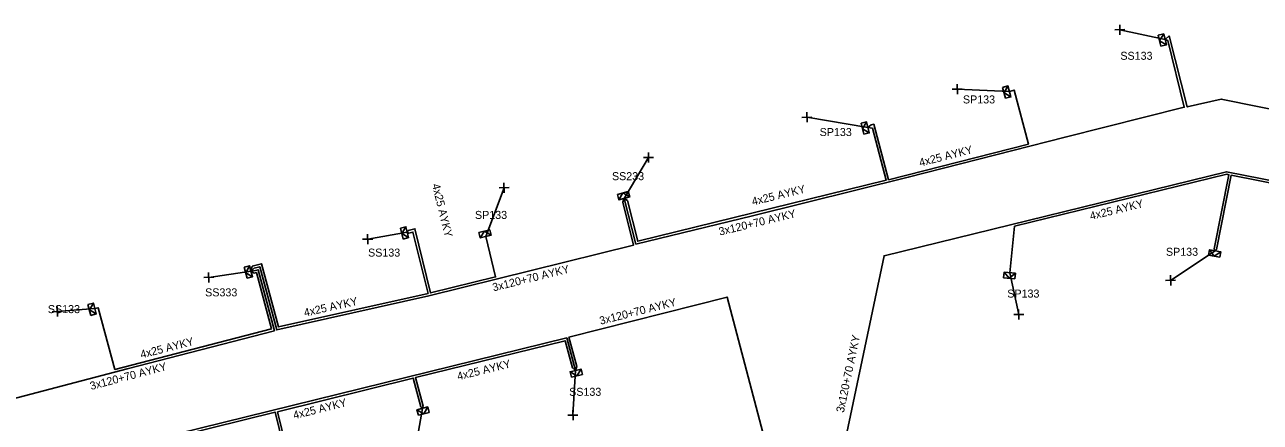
# Model space of a CAD drawing. Extents: x -762500 to -761285, y -1155006 to -1154135.
# Drawn here: x -762207.7 to -762054.2, y -1154659.6 to -1154610.3 of the extents above; entities that cross this region are included whole.
import ezdxf

# ---------------------------------------------------------------- set-up
doc = ezdxf.new("R2010")
doc.units = 0
for name, color, linetype in [('Vrstva 31', 7, 'Continuous'), ('Vrstva 33', 7, 'Continuous'), ('Vrstva 34', 7, 'Continuous'), ('Vrstva 5', 7, 'Continuous'), ('Vrstva 59', 7, 'Continuous'), ('Vrstva 6', 7, 'Continuous')]:
    doc.layers.add(name, color=color, linetype=linetype)

msp = doc.modelspace()

# ---------------------------------------------------------------- linework, layer by layer
at = {"layer": 'Vrstva 31'}
for points in [[(-762066.92, -1154611.568), (-762066.24, -1154611.398), (-762065.902, -1154612.757), (-762066.581, -1154612.926)], [(-762066.92, -1154611.568), (-762066.581, -1154612.926)], [(-762066.75, -1154612.247), (-762066.24, -1154611.398)], [(-762066.75, -1154612.247), (-762065.902, -1154612.757)], [(-762086.258, -1154618.042), (-762085.582, -1154617.861), (-762085.22, -1154619.213), (-762085.896, -1154619.395)], [(-762086.258, -1154618.042), (-762085.896, -1154619.395)], [(-762086.077, -1154618.719), (-762085.582, -1154617.861)], [(-762086.077, -1154618.719), (-762085.22, -1154619.213)], [(-762103.83, -1154622.497), (-762103.151, -1154622.328), (-762102.812, -1154623.686), (-762103.491, -1154623.855)], [(-762103.83, -1154622.497), (-762103.491, -1154623.855)], [(-762103.661, -1154623.176), (-762103.151, -1154622.328)], [(-762103.661, -1154623.176), (-762102.812, -1154623.686)], [(-762132.753, -1154630.971), (-762134.105, -1154631.333)], [(-762132.753, -1154630.971), (-762132.571, -1154631.647), (-762133.924, -1154632.01), (-762134.105, -1154631.333)], [(-762133.429, -1154631.152), (-762133.924, -1154632.01)], [(-762133.429, -1154631.152), (-762132.571, -1154631.647)], [(-762161.06, -1154635.507), (-762160.381, -1154635.338), (-762160.042, -1154636.696), (-762160.721, -1154636.866)], [(-762161.06, -1154635.507), (-762160.721, -1154636.866)], [(-762160.891, -1154636.187), (-762160.381, -1154635.338)], [(-762160.891, -1154636.187), (-762160.042, -1154636.696)], [(-762149.947, -1154635.71), (-762151.306, -1154636.049)], [(-762149.947, -1154635.71), (-762149.778, -1154636.389), (-762151.136, -1154636.728), (-762151.306, -1154636.049)], [(-762150.626, -1154635.88), (-762151.136, -1154636.728)], [(-762150.626, -1154635.88), (-762149.778, -1154636.389)], [(-762060.654, -1154638.887), (-762060.532, -1154638.198), (-762059.154, -1154638.441), (-762059.275, -1154639.13)], [(-762060.654, -1154638.887), (-762059.275, -1154639.13)], [(-762059.965, -1154639.009), (-762060.532, -1154638.198)], [(-762059.965, -1154639.009), (-762059.154, -1154638.441)], [(-762180.468, -1154640.372), (-762179.792, -1154640.191), (-762179.43, -1154641.543), (-762180.106, -1154641.725)], [(-762180.468, -1154640.372), (-762180.106, -1154641.725)], [(-762180.287, -1154641.048), (-762179.792, -1154640.191)], [(-762180.287, -1154641.048), (-762179.43, -1154641.543)], [(-762086.122, -1154641.673), (-762086.049, -1154640.977), (-762084.657, -1154641.123), (-762084.73, -1154641.82)], [(-762085.426, -1154641.746), (-762086.049, -1154640.977)], [(-762085.426, -1154641.746), (-762084.657, -1154641.123)], [(-762086.122, -1154641.673), (-762084.73, -1154641.82)], [(-762199.888, -1154645.002), (-762199.212, -1154644.821), (-762198.85, -1154646.173), (-762199.526, -1154646.354)], [(-762199.888, -1154645.002), (-762199.526, -1154646.354)], [(-762199.707, -1154645.678), (-762199.212, -1154644.821)], [(-762199.707, -1154645.678), (-762198.85, -1154646.173)], [(-762139.812, -1154654.04), (-762139.982, -1154653.36), (-762138.623, -1154653.022), (-762138.454, -1154653.701)], [(-762139.133, -1154653.87), (-762139.982, -1154653.36)], [(-762139.133, -1154653.87), (-762138.623, -1154653.022)], [(-762139.812, -1154654.04), (-762138.454, -1154653.701)], [(-762158.828, -1154658.759), (-762159.009, -1154658.083), (-762157.657, -1154657.72), (-762157.476, -1154658.397)], [(-762158.152, -1154658.578), (-762157.657, -1154657.72)], [(-762158.152, -1154658.578), (-762159.009, -1154658.083)], [(-762158.828, -1154658.759), (-762157.476, -1154658.397)]]:
    msp.add_lwpolyline(points, dxfattribs=at)
at = {"layer": 'Vrstva 34'}
for points in [[(-762071.679, -1154611.505), (-762071.701, -1154610.255)], [(-762072.315, -1154610.891), (-762071.065, -1154610.869)], [(-762091.869, -1154618.875), (-762091.891, -1154617.625)], [(-762092.505, -1154618.261), (-762091.255, -1154618.239)], [(-762110.549, -1154622.375), (-762110.571, -1154621.125)], [(-762111.185, -1154621.761), (-762109.935, -1154621.739)], [(-762130.875, -1154626.761), (-762129.625, -1154626.739)], [(-762130.239, -1154627.375), (-762130.261, -1154626.125)], [(-762148.179, -1154631.125), (-762148.201, -1154629.875)], [(-762148.815, -1154630.511), (-762147.565, -1154630.489)], [(-762165.119, -1154637.505), (-762165.141, -1154636.255)], [(-762165.755, -1154636.891), (-762164.505, -1154636.869)], [(-762184.869, -1154642.255), (-762184.891, -1154641.005)], [(-762185.505, -1154641.641), (-762184.255, -1154641.619)], [(-762066.005, -1154642.011), (-762064.755, -1154641.989)], [(-762065.369, -1154642.625), (-762065.391, -1154641.375)], [(-762203.679, -1154646.505), (-762203.701, -1154645.255)], [(-762084.239, -1154646.875), (-762084.261, -1154645.625)], [(-762204.315, -1154645.891), (-762203.065, -1154645.869)], [(-762084.875, -1154646.261), (-762083.625, -1154646.239)], [(-762140.255, -1154658.761), (-762139.005, -1154658.739)], [(-762139.619, -1154659.375), (-762139.641, -1154658.125)]]:
    msp.add_lwpolyline(points, dxfattribs=at)
at = {"layer": 'Vrstva 5'}
for points in [[(-762014.3, -1154621.08), (-762015.05, -1154620.95), (-762016.45, -1154628.07), (-762035.28, -1154624.27), (-762044.53, -1154622.42), (-762059.09, -1154619.49), (-762063.31, -1154620.47), (-762065.57, -1154611.64), (-762066.07, -1154612.08), (-762065.74, -1154612.2), (-762063.68, -1154620.51), (-762078.48, -1154624.21), (-762097.97, -1154629.2), (-762117.33, -1154634), (-762131.8, -1154637.5), (-762133.25, -1154631.83)], [(-762133.25, -1154631.83), (-762132.87, -1154632.1), (-762131.58, -1154637.14), (-762100.71, -1154629.57), (-762102.43, -1154623.11), (-762102.98, -1154623.01), (-762102.56, -1154622.7), (-762102.25, -1154622.61), (-762100.42, -1154629.51), (-762083.05, -1154625.07), (-762084.82, -1154618.37), (-762085.4, -1154618.54)], [(-762018.03, -1154646.45), (-762017.58, -1154646.23), (-762016.49, -1154646.47), (-762014.67, -1154637.34), (-762032.87, -1154633.54), (-762058.42, -1154628.52), (-762100.97, -1154638.95), (-762109.63, -1154679.98), (-762106.75, -1154684.45), (-762093.8, -1154686.97), (-762093.14, -1154686.59)], [(-762018.03, -1154646.45), (-762017.74, -1154645.89), (-762016.72, -1154646.11), (-762015.02, -1154637.57), (-762032.64, -1154633.9), (-762034.29, -1154641.96), (-762035.28, -1154641.78), (-762035.4, -1154641.56), (-762035.09, -1154641.51), (-762034.53, -1154641.61), (-762032.93, -1154633.85), (-762057.86, -1154628.94), (-762059.66, -1154638.15), (-762059.84, -1154638.32), (-762059.95, -1154638.09), (-762058.14, -1154628.89), (-762058.41, -1154628.83), (-762084.76, -1154635.28), (-762085.35, -1154641.05)], [(-762133.25, -1154631.83), (-762133.45, -1154632.29), (-762132.09, -1154637.62), (-762157.55, -1154643.93), (-762176.42, -1154648.15), (-762178.53, -1154640.31), (-762179.23, -1154640.5), (-762179.61, -1154640.87)], [(-762179.61, -1154640.87), (-762179.48, -1154640.25), (-762178.32, -1154639.94), (-762176.2, -1154647.79), (-762157.62, -1154643.63), (-762159.5, -1154636.01), (-762160.01, -1154636.14), (-762160.21, -1154636.02), (-762160.08, -1154635.81), (-762159.27, -1154635.6), (-762157.33, -1154643.57), (-762149.24, -1154641.58), (-762150.46, -1154636.56)], [(-762179.61, -1154640.87), (-762179.07, -1154640.76), (-762178.74, -1154640.68), (-762176.71, -1154648.25), (-762194.99, -1154652.98), (-762214.28, -1154658.05), (-762215.36, -1154658.34), (-762217.56, -1154649.51), (-762218.27, -1154649.71), (-762218.34, -1154649.89)], [(-762199.03, -1154645.5), (-762198.62, -1154645.4), (-762196.53, -1154653.07), (-762177.08, -1154648.04), (-762178.95, -1154641.04), (-762179.24, -1154641.1), (-762179.61, -1154640.87)], [(-762139.3, -1154653.19), (-762139.13, -1154652.68), (-762140.12, -1154649.04), (-762120.48, -1154644.08), (-762115.24, -1154663.87), (-762118.83, -1154679.7), (-762119.29, -1154679.92)], [(-762223.4, -1154669.64), (-762222.98, -1154669.48), (-762140.4, -1154649.15), (-762139.3, -1154653.19)], [(-762139.3, -1154653.19), (-762139.7, -1154652.86), (-762140.61, -1154649.51), (-762159.19, -1154654.08), (-762158.25, -1154657.62), (-762158.33, -1154657.9), (-762158.54, -1154657.7), (-762159.49, -1154654.13), (-762176.33, -1154658.33), (-762174.77, -1154664.73), (-762175.35, -1154664.79), (-762175.14, -1154664.47), (-762176.64, -1154658.36), (-762192.36, -1154662.25), (-762190.04, -1154671.92), (-762190.54, -1154672.04)]]:
    msp.add_lwpolyline(points, dxfattribs=at)
at = {"layer": 'Vrstva 59'}
for points in [[(-762066.07, -1154612.08), (-762071.69, -1154610.88)], [(-762085.4, -1154618.54), (-762091.88, -1154618.25)], [(-762102.98, -1154623.01), (-762110.56, -1154621.75)], [(-762133.25, -1154631.83), (-762130.25, -1154626.75)], [(-762150.46, -1154636.56), (-762148.19, -1154630.5)], [(-762160.21, -1154636.02), (-762165.13, -1154636.88)], [(-762059.84, -1154638.32), (-762065.38, -1154642)], [(-762179.61, -1154640.87), (-762184.88, -1154641.63)], [(-762085.35, -1154641.05), (-762084.25, -1154646.25)], [(-762199.03, -1154645.5), (-762203.69, -1154645.88)], [(-762139.3, -1154653.19), (-762139.63, -1154658.75)], [(-762158.33, -1154657.9), (-762159.44, -1154664.25)]]:
    msp.add_lwpolyline(points, dxfattribs=at)

# ---------------------------------------------------------------- texts
at = {"layer": 'Vrstva 33'}
for s, p in [('SS133', (-762071.62, -1154614.61)), ('SP133', (-762091.18, -1154620.03)), ('SP133', (-762108.98, -1154624.08)), ('SS233', (-762134.78, -1154629.56)), ('SP133', (-762151.8, -1154634.37)), ('SS133', (-762165.08, -1154639.05)), ('SP133', (-762065.96, -1154638.95)), ('SS333', (-762185.32, -1154643.99)), ('SP133', (-762085.67, -1154644.14)), ('SS133', (-762204.86, -1154646.07)), ('SS133', (-762140.1, -1154656.34))]:
    msp.add_text(s, height=0.9943, dxfattribs=at).set_placement(p)
at = {"layer": 'Vrstva 6'}
for s, height, rotation, p in [('4x25 AYKY', 0.9943, 14.33846, (-762096.49, -1154627.88)), ('4x25 AYKY', 0.9943, 283.84118, (-762157.15, -1154630.12)), ('4x25 AYKY', 0.9943, 13.78622, (-762117.28, -1154632.71)), ('3x120+70 AYKY', 0.99428, 13.62292, (-762121.38, -1154636.45)), ('4x25 AYKY', 0.9943, 13.75915, (-762075.29, -1154634.51)), ('3x120+70 AYKY', 0.99429, 13.93613, (-762149.5, -1154643.38)), ('4x25 AYKY', 0.9943, 12.61564, (-762172.94, -1154646.51)), ('3x120+70 AYKY', 0.99428, 14.16729, (-762136.2, -1154647.52)), ('3x120+70 AYKY', 0.99429, 78.09206, (-762105.98, -1154658.49)), ('4x25 AYKY', 0.9943, 14.49141, (-762193.24, -1154651.71)), ('4x25 AYKY', 0.9943, 13.84086, (-762153.89, -1154654.42)), ('3x120+70 AYKY', 0.99429, 14.74605, (-762199.49, -1154655.62)), ('4x25 AYKY', 0.9943, 13.9914, (-762174.26, -1154659.25))]:
    msp.add_text(s, height=height, rotation=rotation, dxfattribs=at).set_placement(p)

doc.saveas('drawing.dxf')
